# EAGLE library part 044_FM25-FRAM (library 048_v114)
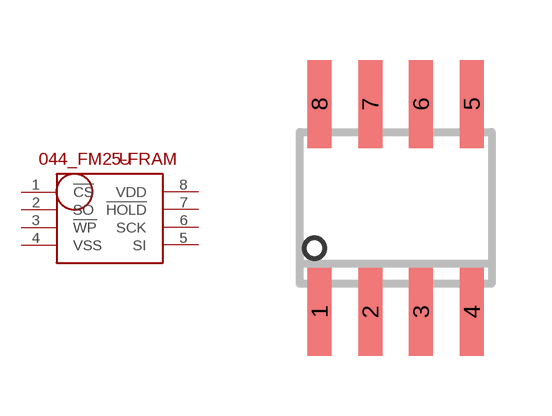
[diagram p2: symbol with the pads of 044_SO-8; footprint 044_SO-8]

Designator prefix -

## 044_FM25-FRAM  [044_SO-8]
1  !CS
2  SO
3  !WP
4  VSS  pwr
5  SI
6  SCK
7  !HOLD
8  VDD  pwr

## Footprint 044_SO-8 (pad centres in mm)
smd 0.6 x 2.2: 1 -1.905,-2.6; 2 -0.635,-2.6; 3 0.635,-2.6; 4 1.905,-2.6; 5 1.905,2.6; 6 0.635,2.6; 7 -0.635,2.6; 8 -1.905,2.6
